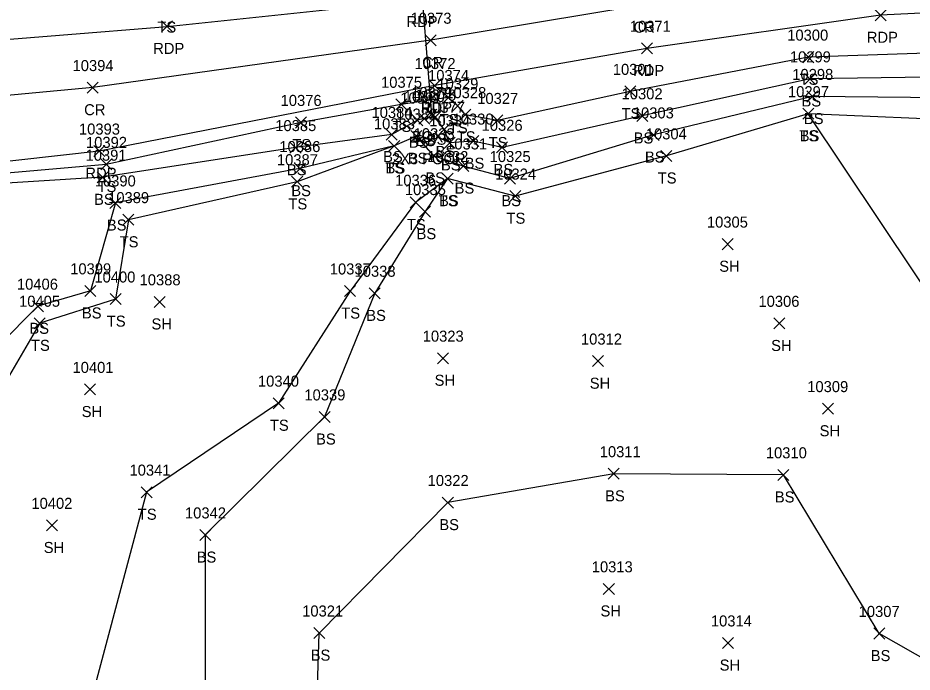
# Model space of a CAD drawing. Extents: x 1475671 to 1477951, y 592661 to 593821.
# Drawn here: x 1476578.6 to 1476740.9, y 592957 to 593075.6 of the extents above; entities that cross this region are included whole.
import ezdxf

# ---------------------------------------------------------------- set-up
doc = ezdxf.new("R2010")
doc.units = 0
for name, color, linetype in [('D_A', 7, 'Continuous'), ('D_C', 7, 'Continuous'), ('D_I', 7, 'Continuous'), ('D_TIC', 7, 'Continuous'), ('DCP', 7, 'Continuous'), ('L_A', 7, 'Continuous'), ('L_I', 7, 'Continuous'), ('L_TIC', 7, 'Continuous'), ('LELB', 7, 'Continuous'), ('P_A', 7, 'Continuous'), ('P_I', 7, 'Continuous'), ('P_TIC', 7, 'Continuous'), ('PET', 7, 'Continuous'), ('PRC', 7, 'Continuous')]:
    doc.layers.add(name, color=color, linetype=linetype)

msp = doc.modelspace()

# ---------------------------------------------------------------- linework, layer by layer
at = {"layer": 'D_TIC'}
for points in [[(1476652.65, 593057.02), (1476654.65, 593059.02)], [(1476654.65, 593057.02), (1476652.65, 593059.02)]]:
    msp.add_lwpolyline(points, dxfattribs=at)
at = {"layer": 'DCP'}
msp.add_lwpolyline([(1476651.34, 593087.34), (1476653.65, 593058.02)], dxfattribs=at)
at = {"layer": 'L_TIC'}
for points in [[(1476721.06, 593067.43), (1476723.06, 593069.43)], [(1476723.06, 593067.43), (1476721.06, 593069.43)], [(1476721.37, 593063.49), (1476723.37, 593065.49)], [(1476723.37, 593063.49), (1476721.37, 593065.49)], [(1476655.72, 593060.12), (1476657.72, 593062.12)], [(1476657.72, 593060.12), (1476655.72, 593062.12)], [(1476655.72, 593060.12), (1476657.72, 593062.12)], [(1476657.72, 593060.12), (1476655.72, 593062.12)], [(1476688.75, 593061.22), (1476690.75, 593063.22)], [(1476690.75, 593061.22), (1476688.75, 593063.22)], [(1476721.8, 593060.3), (1476723.8, 593062.3)], [(1476723.8, 593060.3), (1476721.8, 593062.3)], [(1476647.18, 593058.88), (1476649.18, 593060.88)], [(1476649.18, 593058.88), (1476647.18, 593060.88)], [(1476657.42, 593058.61), (1476659.42, 593060.61)], [(1476659.42, 593058.61), (1476657.42, 593060.61)], [(1476653.36, 593056.56), (1476655.36, 593058.56)], [(1476655.36, 593056.56), (1476653.36, 593058.56)], [(1476658.84, 593057), (1476660.84, 593059)], [(1476660.84, 593057), (1476658.84, 593059)], [(1476690.91, 593056.79), (1476692.91, 593058.79)], [(1476692.91, 593056.79), (1476690.91, 593058.79)], [(1476721.03, 593057.18), (1476723.03, 593059.18)], [(1476723.03, 593057.18), (1476721.03, 593059.18)], [(1476721.03, 593057.18), (1476723.03, 593059.18)], [(1476723.03, 593057.18), (1476721.03, 593059.18)], [(1476629.02, 593055.59), (1476631.02, 593057.59)], [(1476631.02, 593055.59), (1476629.02, 593057.59)], [(1476650.11, 593056.01), (1476652.11, 593058.01)], [(1476652.11, 593056.01), (1476650.11, 593058.01)], [(1476651.4, 593056.3), (1476653.4, 593058.3)], [(1476653.4, 593056.3), (1476651.4, 593058.3)], [(1476664.64, 593055.95), (1476666.64, 593057.95)], [(1476666.64, 593055.95), (1476664.64, 593057.95)], [(1476645.46, 593053.41), (1476647.46, 593055.41)], [(1476647.46, 593053.41), (1476645.46, 593055.41)], [(1476654.98, 593054.35), (1476656.98, 593056.35)], [(1476656.98, 593054.35), (1476654.98, 593056.35)], [(1476692.96, 593053.33), (1476694.96, 593055.33)], [(1476694.96, 593053.33), (1476692.96, 593055.33)], [(1476649.93, 593053.11), (1476651.93, 593055.11)], [(1476651.93, 593053.11), (1476649.93, 593055.11)], [(1476655.95, 593051.9), (1476657.95, 593053.9)], [(1476657.95, 593051.9), (1476655.95, 593053.9)], [(1476660.25, 593052.21), (1476662.25, 593054.21)], [(1476662.25, 593052.21), (1476660.25, 593054.21)], [(1476628, 593051.03), (1476630, 593053.03)], [(1476630, 593051.03), (1476628, 593053.03)], [(1476645.9, 593051.35), (1476647.9, 593053.35)], [(1476647.9, 593051.35), (1476645.9, 593053.35)], [(1476645.9, 593051.35), (1476647.9, 593053.35)], [(1476647.9, 593051.35), (1476645.9, 593053.35)], [(1476665.49, 593051.08), (1476667.49, 593053.08)], [(1476667.49, 593051.08), (1476665.49, 593053.08)], [(1476653.11, 593049.55), (1476655.11, 593051.55)], [(1476655.11, 593049.55), (1476653.11, 593051.55)], [(1476695.31, 593049.53), (1476697.31, 593051.53)], [(1476697.31, 593049.53), (1476695.31, 593051.53)], [(1476593.66, 593047.99), (1476595.66, 593049.99)], [(1476595.66, 593047.99), (1476593.66, 593049.99)], [(1476628.79, 593047.23), (1476630.79, 593049.23)], [(1476630.79, 593047.23), (1476628.79, 593049.23)], [(1476658.43, 593047.7), (1476660.43, 593049.7)], [(1476660.43, 593047.7), (1476658.43, 593049.7)], [(1476593.01, 593045.66), (1476595.01, 593047.66)], [(1476595.01, 593045.66), (1476593.01, 593047.66)], [(1476655.59, 593045.41), (1476657.59, 593047.41)], [(1476657.59, 593045.41), (1476655.59, 593047.41)], [(1476655.59, 593045.41), (1476657.59, 593047.41)], [(1476657.59, 593045.41), (1476655.59, 593047.41)], [(1476666.9, 593045.42), (1476668.9, 593047.42)], [(1476668.9, 593045.42), (1476666.9, 593047.42)], [(1476628.3, 593044.84), (1476630.3, 593046.84)], [(1476630.3, 593044.84), (1476628.3, 593046.84)], [(1476667.87, 593042.24), (1476669.87, 593044.24)], [(1476669.87, 593042.24), (1476667.87, 593044.24)], [(1476595.33, 593041), (1476597.33, 593043)], [(1476597.33, 593041), (1476595.33, 593043)], [(1476649.8, 593041.11), (1476651.8, 593043.11)], [(1476651.8, 593041.11), (1476649.8, 593043.11)], [(1476651.52, 593039.43), (1476653.52, 593041.43)], [(1476653.52, 593039.43), (1476651.52, 593041.43)], [(1476597.68, 593037.97), (1476599.68, 593039.97)], [(1476599.68, 593037.97), (1476597.68, 593039.97)], [(1476706.39, 593033.53), (1476708.39, 593035.53)], [(1476708.39, 593033.53), (1476706.39, 593035.53)], [(1476590.8, 593025.06), (1476592.8, 593027.06)], [(1476592.8, 593025.06), (1476590.8, 593027.06)], [(1476637.89, 593025.04), (1476639.89, 593027.04)], [(1476639.89, 593025.04), (1476637.89, 593027.04)], [(1476642.39, 593024.62), (1476644.39, 593026.62)], [(1476644.39, 593024.62), (1476642.39, 593026.62)], [(1476595.35, 593023.58), (1476597.35, 593025.58)], [(1476597.35, 593023.58), (1476595.35, 593025.58)], [(1476603.38, 593023.07), (1476605.38, 593025.07)], [(1476605.38, 593023.07), (1476603.38, 593025.07)], [(1476581.27, 593022.28), (1476583.27, 593024.28)], [(1476583.27, 593022.28), (1476581.27, 593024.28)], [(1476581.59, 593019.19), (1476583.59, 593021.19)], [(1476583.59, 593019.19), (1476581.59, 593021.19)], [(1476715.81, 593019.17), (1476717.81, 593021.17)], [(1476717.81, 593019.17), (1476715.81, 593021.17)], [(1476654.75, 593012.86), (1476656.75, 593014.86)], [(1476656.75, 593012.86), (1476654.75, 593014.86)], [(1476682.9, 593012.33), (1476684.9, 593014.33)], [(1476684.9, 593012.33), (1476682.9, 593014.33)], [(1476590.72, 593007.19), (1476592.72, 593009.19)], [(1476592.72, 593007.19), (1476590.72, 593009.19)], [(1476624.94, 593004.7), (1476626.94, 593006.7)], [(1476626.94, 593004.7), (1476624.94, 593006.7)], [(1476724.61, 593003.71), (1476726.61, 593005.71)], [(1476726.61, 593003.71), (1476724.61, 593005.71)], [(1476633.29, 593002.21), (1476635.29, 593004.21)], [(1476635.29, 593002.21), (1476633.29, 593004.21)], [(1476685.74, 592991.91), (1476687.74, 592993.91)], [(1476687.74, 592991.91), (1476685.74, 592993.91)], [(1476716.53, 592991.71), (1476718.53, 592993.71)], [(1476718.53, 592991.71), (1476716.53, 592993.71)], [(1476600.98, 592988.57), (1476602.98, 592990.57)], [(1476602.98, 592988.57), (1476600.98, 592990.57)], [(1476655.64, 592986.69), (1476657.64, 592988.69)], [(1476657.64, 592986.69), (1476655.64, 592988.69)], [(1476655.64, 592986.69), (1476657.64, 592988.69)], [(1476657.64, 592986.69), (1476655.64, 592988.69)], [(1476583.83, 592982.55), (1476585.83, 592984.55)], [(1476585.83, 592982.55), (1476583.83, 592984.55)], [(1476611.62, 592980.81), (1476613.62, 592982.81)], [(1476613.62, 592980.81), (1476611.62, 592982.81)], [(1476684.85, 592971.04), (1476686.85, 592973.04)], [(1476686.85, 592971.04), (1476684.85, 592973.04)], [(1476632.31, 592963.03), (1476634.31, 592965.03)], [(1476634.31, 592963.03), (1476632.31, 592965.03)], [(1476733.93, 592962.95), (1476735.93, 592964.95)], [(1476735.93, 592962.95), (1476733.93, 592964.95)], [(1476706.47, 592961.23), (1476708.47, 592963.23)], [(1476708.47, 592961.23), (1476706.47, 592963.23)]]:
    msp.add_lwpolyline(points, dxfattribs=at)
at = {"layer": 'LELB'}
for points in [[(1476780.76, 593069.19), (1476752.47, 593069.45), (1476722.06, 593068.43), (1476689.75, 593062.22), (1476665.64, 593056.95), (1476659.84, 593058), (1476658.42, 593059.61), (1476656.72, 593061.12)], [(1476841.85, 593018.32), (1476825.12, 593035.12), (1476811.51, 593051.32), (1476779.42, 593062.14), (1476752.49, 593064.9), (1476722.37, 593064.49), (1476691.91, 593057.79), (1476666.49, 593052.08), (1476661.25, 593053.21), (1476656.95, 593052.9), (1476655.98, 593055.35), (1476654.36, 593057.56), (1476652.4, 593057.3), (1476651.11, 593057.01), (1476646.46, 593054.41), (1476629, 593052.03), (1476594.01, 593046.66), (1476557.34, 593044.4), (1476521.14, 593041.18), (1476464.22, 593030.64)], [(1476656.72, 593061.12), (1476648.18, 593059.88), (1476630.02, 593056.59), (1476594.66, 593048.99), (1476557.23, 593045.74), (1476521.08, 593042.35), (1476462.84, 593033.95), (1476419.94, 593027.86), (1476367.81, 593018.54), (1476319.05, 593010.3), (1476266.9, 593001.04), (1476164.01, 592984.31)], [(1476839.39, 593010.15), (1476820.84, 593030.96), (1476810.95, 593047.74), (1476779.57, 593058.62), (1476752.41, 593061.01), (1476722.8, 593061.3), (1476693.96, 593054.33), (1476667.9, 593046.42), (1476659.43, 593048.7), (1476654.11, 593050.55), (1476650.93, 593054.11), (1476646.9, 593052.35), (1476629.79, 593048.23), (1476596.33, 593042), (1476591.8, 593026.06), (1476582.27, 593023.28), (1476575.03, 593016.09), (1476569.43, 592997.76), (1476547.37, 592959.22)], [(1476807.42, 593044.4), (1476778.65, 593056.41), (1476752.9, 593056.84), (1476722.03, 593058.18), (1476696.31, 593050.53), (1476668.87, 593043.24), (1476656.59, 593046.41), (1476650.8, 593042.11), (1476638.89, 593026.04), (1476625.94, 593005.7), (1476601.98, 592989.57), (1476589.47, 592942.63), (1476588.41, 592908.01)], [(1476827.26, 592834.12), (1476835.32, 592879.17), (1476841.26, 592896.75), (1476832.77, 592915.24), (1476825.78, 592945.91), (1476820.93, 592965.41), (1476796.57, 592984.14), (1476754.48, 593009.66), (1476722.03, 593058.18)], [(1476646.9, 593052.35), (1476629.3, 593045.84), (1476598.68, 593038.97), (1476596.35, 593024.58), (1476582.59, 593020.19), (1476569.43, 592997.76)], [(1476656.59, 593046.41), (1476652.52, 593040.43), (1476643.39, 593025.62), (1476634.29, 593003.21), (1476612.62, 592981.81), (1476612.63, 592947.46), (1476610.49, 592911.01)], [(1476850.04, 592796.99), (1476834.85, 592814.45), (1476832.4, 592817.5), (1476827.26, 592834.12), (1476804.05, 592871.04), (1476800.09, 592907.29), (1476764.33, 592947.22), (1476734.93, 592963.95), (1476717.53, 592992.71), (1476686.74, 592992.91), (1476656.64, 592987.69)], [(1476631.05, 592909.69), (1476632.45, 592936.79), (1476633.31, 592964.03), (1476656.64, 592987.69)]]:
    msp.add_lwpolyline(points, dxfattribs=at)
at = {"layer": 'P_TIC'}
for points in [[(1476734.17, 593075.04), (1476736.17, 593077.04)], [(1476736.17, 593075.04), (1476734.17, 593077.04)], [(1476604.7, 593073.02), (1476606.7, 593075.02)], [(1476606.7, 593073.02), (1476604.7, 593075.02)], [(1476652.54, 593070.49), (1476654.54, 593072.49)], [(1476654.54, 593070.49), (1476652.54, 593072.49)], [(1476691.75, 593069.03), (1476693.75, 593071.03)], [(1476693.75, 593069.03), (1476691.75, 593071.03)], [(1476591.22, 593061.91), (1476593.22, 593063.91)], [(1476593.22, 593061.91), (1476591.22, 593063.91)], [(1476653.27, 593062.28), (1476655.27, 593064.28)], [(1476655.27, 593062.28), (1476653.27, 593064.28)], [(1476592.38, 593050.4), (1476594.38, 593052.4)], [(1476594.38, 593050.4), (1476592.38, 593052.4)]]:
    msp.add_lwpolyline(points, dxfattribs=at)
at = {"layer": 'PET'}
for points in [[(1476550.12, 593088.22), (1476546.99, 593080.79), (1476546.62, 593074.3), (1476558.02, 593070.45), (1476566.6, 593070.83), (1476605.7, 593074.02), (1476651.65, 593078.89), (1476683.81, 593086.28), (1476716.78, 593091.72), (1476756.3, 593096.32), (1476786.76, 593094.61), (1476795.52, 593092.66), (1476816.88, 593085.29), (1476835.43, 593074.22), (1476828.62, 593102.02), (1476824.42, 593119.75), (1476821.59, 593140.77), (1476821.02, 593163.56), (1476821.92, 593180.44), (1476827.12, 593207.84), (1476837.47, 593243.39), (1476848.83, 593278.3), (1476858.44, 593303.19), (1476868.19, 593333.86)], [(1476876.69, 592931.37), (1476866.39, 592975.94), (1476855.42, 593012.87), (1476851.35, 593023.14), (1476844.63, 593035.78), (1476834.27, 593048.7), (1476823.42, 593058.99), (1476807.6, 593067.92), (1476802.87, 593070.05), (1476785.81, 593074.83), (1476762.31, 593077.35), (1476735.17, 593076.04), (1476692.75, 593070.03), (1476654.27, 593063.28), (1476593.38, 593051.4), (1476557.14, 593047.34), (1476521.33, 593044.37), (1476462.5, 593038.2)]]:
    msp.add_lwpolyline(points, dxfattribs=at)
at = {"layer": 'PRC'}
msp.add_lwpolyline([(1476783.7, 593084.94), (1476761.58, 593086.67), (1476734.11, 593084.66), (1476691.9, 593077.87), (1476653.54, 593071.49), (1476592.22, 593062.91), (1476555.36, 593059.5), (1476520.45, 593058.11), (1476501.29, 593059.51), (1476493.61, 593061.9)], dxfattribs=at)

# ---------------------------------------------------------------- texts
at = {"layer": 'D_A'}
msp.add_text('BOXC', height=2, dxfattribs=at).set_placement((1476650.15, 593053.02))
at = {"layer": 'D_C'}
msp.add_text('2X3 POOR', height=2, dxfattribs=at).set_placement((1476646.48, 593049.02))
at = {"layer": 'D_I'}
msp.add_text('10379', height=2, dxfattribs=at).set_placement((1476649.98, 593061.02))
at = {"layer": 'L_A'}
for s, p in [('TS', (1476603.94, 593072.89)), ('TS', (1476720.47, 593063.43)), ('BS', (1476720.81, 593059.49)), ('TS', (1476688.16, 593057.22)), ('TS', (1476646.59, 593054.88)), ('TS', (1476655.13, 593056.12)), ('TS', (1476655.13, 593056.12)), ('BS', (1476721.24, 593056.3)), ('TS', (1476656.83, 593054.61)), ('BS', (1476649.55, 593052.01)), ('BS', (1476650.84, 593052.3)), ('BS', (1476652.81, 593052.56)), ('TS', (1476658.25, 593053)), ('TS', (1476664.05, 593051.95)), ('BS', (1476690.35, 593052.79)), ('TS', (1476720.44, 593053.18)), ('BS', (1476720.47, 593053.18)), ('TS', (1476628.43, 593051.59)), ('BS', (1476654.42, 593050.35)), ('BS', (1476644.9, 593049.41)), ('BS', (1476649.37, 593049.11)), ('BS', (1476692.4, 593049.33)), ('BS', (1476627.44, 593047.03)), ('TS', (1476645.3, 593047.35)), ('BS', (1476645.34, 593047.35)), ('BS', (1476655.39, 593047.9)), ('BS', (1476659.69, 593048.21)), ('BS', (1476664.93, 593047.08)), ('BS', (1476652.55, 593045.55)), ('TS', (1476694.72, 593045.53)), ('TS', (1476593.07, 593043.99)), ('BS', (1476657.87, 593043.7)), ('BS', (1476628.23, 593043.23)), ('BS', (1476592.45, 593041.66)), ('TS', (1476627.71, 593040.84)), ('TS', (1476655, 593041.41)), ('BS', (1476655.03, 593041.41)), ('BS', (1476666.34, 593041.42)), ('TS', (1476649.21, 593037.11)), ('TS', (1476667.28, 593038.24)), ('BS', (1476594.77, 593037)), ('BS', (1476650.96, 593035.43)), ('TS', (1476597.09, 593033.97)), ('SH', (1476705.88, 593029.53)), ('BS', (1476590.24, 593021.06)), ('TS', (1476637.3, 593021.04)), ('TS', (1476594.76, 593019.58)), ('BS', (1476641.83, 593020.62)), ('BS', (1476580.71, 593018.28)), ('SH', (1476602.87, 593019.07)), ('TS', (1476581, 593015.19)), ('SH', (1476715.3, 593015.17)), ('SH', (1476654.24, 593008.86)), ('SH', (1476682.39, 593008.33)), ('SH', (1476590.21, 593003.19)), ('TS', (1476624.35, 593000.7)), ('SH', (1476724.1, 592999.71)), ('BS', (1476632.73, 592998.21)), ('BS', (1476685.18, 592987.91)), ('BS', (1476715.97, 592987.71)), ('TS', (1476600.39, 592984.57)), ('BS', (1476655.09, 592982.69)), ('BS', (1476655.09, 592982.69)), ('SH', (1476583.32, 592978.55)), ('BS', (1476611.06, 592976.81)), ('SH', (1476684.34, 592967.04)), ('BS', (1476631.75, 592959.03)), ('BS', (1476733.37, 592958.95)), ('SH', (1476705.96, 592957.23))]:
    msp.add_text(s, height=2, dxfattribs=at).set_placement(p)
at = {"layer": 'L_I'}
for s, p in [('10300', (1476718.22, 593071.43)), ('10299', (1476718.7, 593067.49)), ('10301', (1476686.57, 593065.22)), ('10374', (1476653.05, 593064.12)), ('10374', (1476653.05, 593064.12)), ('10298', (1476719.13, 593064.3)), ('10375', (1476644.52, 593062.88)), ('10329', (1476654.74, 593062.61)), ('10381', (1476648.01, 593060.01)), ('10380', (1476648.65, 593060.3)), ('10378', (1476650.69, 593060.56)), ('10328', (1476656.17, 593061)), ('10327', (1476661.97, 593059.95)), ('10302', (1476688.17, 593060.79)), ('10297', (1476718.36, 593061.18)), ('10297', (1476718.36, 593061.18)), ('10376', (1476626.3, 593059.59)), ('10377', (1476652.31, 593058.35)), ('10384', (1476642.79, 593057.41)), ('10382', (1476647.26, 593057.11)), ('10303', (1476690.21, 593057.33)), ('10385', (1476625.33, 593055.03)), ('10383', (1476643.23, 593055.35)), ('10383', (1476643.23, 593055.35)), ('10334', (1476653.28, 593055.9)), ('10330', (1476657.5, 593056.21)), ('10326', (1476662.77, 593055.08)), ('10333', (1476650.44, 593053.55)), ('10304', (1476692.56, 593053.53)), ('10392', (1476590.99, 593051.99)), ('10331', (1476656.33, 593051.7)), ('10386', (1476626.07, 593051.23)), ('10391', (1476590.9, 593049.66)), ('10387', (1476625.63, 593048.84)), ('10332', (1476652.92, 593049.41)), ('10332', (1476652.92, 593049.41)), ('10325', (1476664.23, 593049.42)), ('10324', (1476665.21, 593046.24)), ('10390', (1476592.58, 593045)), ('10336', (1476647.07, 593045.11)), ('10389', (1476595, 593041.97)), ('10335', (1476648.85, 593043.43)), ('10305', (1476703.65, 593037.53)), ('10399', (1476588.12, 593029.06)), ('10337', (1476635.22, 593029.04)), ('10400', (1476592.51, 593027.58)), ('10338', (1476639.72, 593028.62)), ('10406', (1476578.46, 593026.28)), ('10388', (1476600.71, 593027.07)), ('10405', (1476578.84, 593023.19)), ('10306', (1476713, 593023.17)), ('10323', (1476652.08, 593016.86)), ('10312', (1476680.8, 593016.33)), ('10401', (1476588.54, 593011.19)), ('10340', (1476622.19, 593008.7)), ('10339', (1476630.61, 593006.21)), ('10309', (1476721.85, 593007.71)), ('10311', (1476684.2, 592995.91)), ('10310', (1476714.34, 592995.71)), ('10341', (1476598.88, 592992.57)), ('10322', (1476652.98, 592990.69)), ('10322', (1476652.98, 592990.69)), ('10402', (1476581.08, 592986.55)), ('10342', (1476608.95, 592984.81)), ('10313', (1476682.75, 592975.04)), ('10321', (1476630.21, 592967.03)), ('10307', (1476731.18, 592966.95)), ('10314', (1476704.37, 592965.23))]:
    msp.add_text(s, height=2, dxfattribs=at).set_placement(p)
at = {"layer": 'P_A'}
for s, p in [('RDP', (1476649.14, 593073.89)), ('CR', (1476690.33, 593072.87)), ('RDP', (1476732.66, 593071.04)), ('RDP', (1476603.18, 593069.02)), ('CR', (1476651.97, 593066.49)), ('RDP', (1476690.24, 593065.03)), ('RDP', (1476651.76, 593058.28)), ('CR', (1476590.65, 593057.91)), ('RDP', (1476590.87, 593046.4))]:
    msp.add_text(s, height=2, dxfattribs=at).set_placement(p)
at = {"layer": 'P_I'}
for s, p in [('10373', (1476649.87, 593074.49)), ('10371', (1476689.65, 593073.03)), ('10372', (1476650.6, 593066.28)), ('10394', (1476588.55, 593065.91)), ('10393', (1476589.71, 593054.4))]:
    msp.add_text(s, height=2, dxfattribs=at).set_placement(p)

doc.saveas('drawing.dxf')
